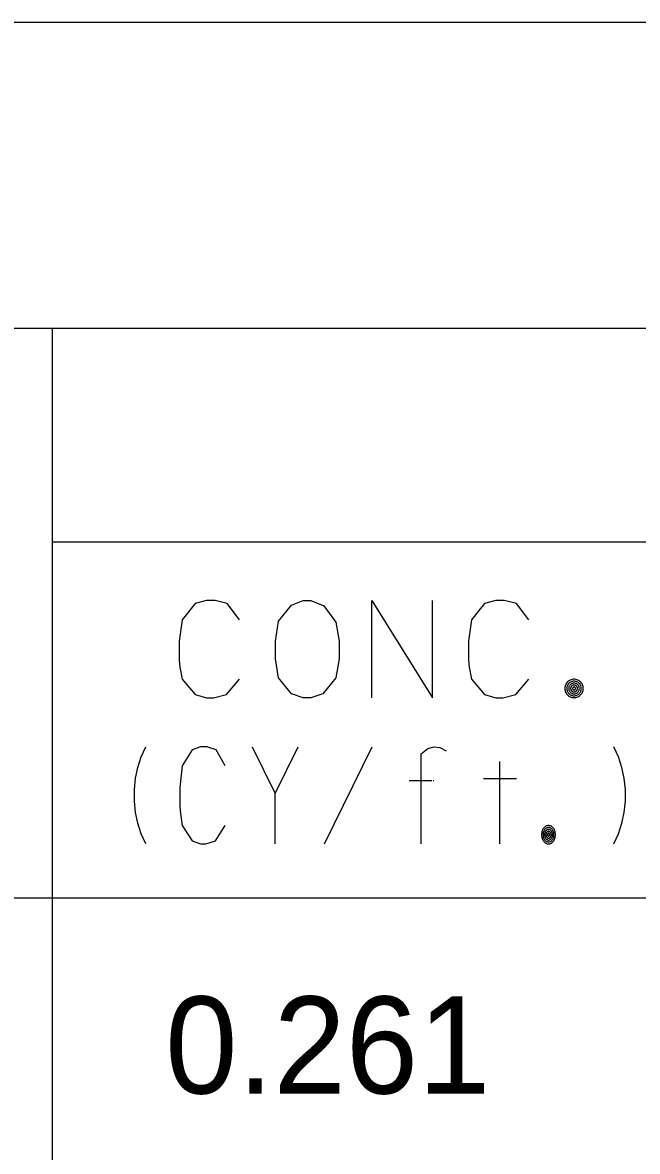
# Model space of a CAD drawing. Extents: x 635698 to 639877, y 296617 to 300175.
# Drawn here: x 639271.19 to 639290.16, y 299135.92 to 299170.8 of the extents above; entities that cross this region are included whole.
import ezdxf

# ---------------------------------------------------------------- set-up
doc = ezdxf.new("R2010")
doc.units = 0
doc.layers.add('1', color=7, linetype='Continuous')
doc.layers.add('3', color=7, linetype='Continuous')

msp = doc.modelspace()

# ---------------------------------------------------------------- linework, layer by layer
at = {"layer": '1'}
for p, q in [((639412.368, 299170.796), (638860.564, 299170.796)), ((639412.368, 299161.344), (639008.767, 299161.344)), ((639272.1, 299161.344), (639272.1, 299029.334)), ((639412.368, 299154.742), (639272.1, 299154.742)), ((639412.368, 299143.742), (639008.767, 299143.742))]:
    msp.add_line(p, q, dxfattribs=at)
at = {"layer": '3'}
for points in [[(639277.883, 299152.348), (639277.506, 299152.844), (639277.128, 299152.939), (639276.868, 299152.939), (639276.513, 299152.844), (639276.112, 299152.348), (639276.017, 299151.687), (639276.017, 299151.333), (639276.017, 299151.096), (639276.041, 299150.884), (639276.112, 299150.506), (639276.513, 299150.033), (639276.868, 299149.939), (639277.08, 299149.939), (639277.482, 299150.033), (639277.883, 299150.506)], [(639279.844, 299152.939), (639280.08, 299152.939), (639280.482, 299152.774), (639280.86, 299152.277), (639280.954, 299151.687), (639280.954, 299151.144), (639280.86, 299150.553), (639280.458, 299150.057), (639280.08, 299149.939), (639279.844, 299149.939), (639279.49, 299150.057), (639279.088, 299150.553), (639278.994, 299151.144), (639278.994, 299151.687), (639279.088, 299152.301), (639279.49, 299152.797), (639279.844, 299152.939)], [(639281.97, 299149.939), (639281.97, 299152.939), (639283.836, 299149.939), (639283.836, 299152.939)], [(639286.813, 299152.348), (639286.435, 299152.844), (639286.057, 299152.939), (639285.797, 299152.939), (639285.443, 299152.844), (639285.041, 299152.348), (639284.947, 299151.687), (639284.947, 299151.333), (639284.947, 299151.096), (639284.971, 299150.884), (639285.041, 299150.506), (639285.443, 299150.033), (639285.797, 299149.939), (639286.01, 299149.939), (639286.411, 299150.033), (639286.813, 299150.506)], [(639288.493, 299150.224), (639288.492, 299150.253), (639288.487, 299150.283), (639288.479, 299150.312), (639288.469, 299150.339), (639288.455, 299150.366), (639288.439, 299150.391), (639288.42, 299150.414), (639288.399, 299150.435), (639288.376, 299150.454), (639288.351, 299150.471), (639288.324, 299150.484), (639288.296, 299150.495), (639288.268, 299150.502), (639288.238, 299150.507), (639288.208, 299150.509), (639288.178, 299150.507), (639288.149, 299150.502), (639288.12, 299150.495), (639288.092, 299150.484), (639288.066, 299150.471), (639288.041, 299150.454), (639288.018, 299150.435), (639287.996, 299150.414), (639287.978, 299150.391), (639287.962, 299150.366), (639287.948, 299150.339), (639287.937, 299150.312), (639287.93, 299150.283), (639287.925, 299150.253), (639287.923, 299150.224), (639287.925, 299150.194), (639287.93, 299150.164), (639287.937, 299150.135), (639287.948, 299150.108), (639287.962, 299150.081), (639287.978, 299150.056), (639287.996, 299150.033), (639288.018, 299150.012), (639288.041, 299149.993), (639288.066, 299149.977), (639288.092, 299149.963), (639288.12, 299149.953), (639288.149, 299149.945), (639288.178, 299149.94), (639288.208, 299149.939), (639288.238, 299149.94), (639288.268, 299149.945), (639288.296, 299149.953), (639288.324, 299149.963), (639288.351, 299149.977), (639288.376, 299149.993), (639288.399, 299150.012), (639288.42, 299150.033), (639288.439, 299150.056), (639288.455, 299150.081), (639288.469, 299150.108), (639288.479, 299150.135), (639288.487, 299150.164), (639288.492, 299150.194), (639288.493, 299150.224)], [(639288.433, 299150.224), (639288.432, 299150.247), (639288.428, 299150.27), (639288.422, 299150.293), (639288.414, 299150.315), (639288.403, 299150.336), (639288.39, 299150.356), (639288.375, 299150.374), (639288.359, 299150.391), (639288.341, 299150.406), (639288.321, 299150.419), (639288.3, 299150.429), (639288.278, 299150.438), (639288.255, 299150.444), (639288.232, 299150.447), (639288.208, 299150.449), (639288.185, 299150.447), (639288.162, 299150.444), (639288.139, 299150.438), (639288.117, 299150.429), (639288.096, 299150.419), (639288.076, 299150.406), (639288.058, 299150.391), (639288.041, 299150.374), (639288.026, 299150.356), (639288.014, 299150.336), (639288.003, 299150.315), (639287.994, 299150.293), (639287.988, 299150.27), (639287.985, 299150.247), (639287.983, 299150.224), (639287.985, 299150.2), (639287.988, 299150.177), (639287.994, 299150.154), (639288.003, 299150.132), (639288.014, 299150.111), (639288.026, 299150.092), (639288.041, 299150.073), (639288.058, 299150.056), (639288.076, 299150.042), (639288.096, 299150.029), (639288.117, 299150.018), (639288.139, 299150.01), (639288.162, 299150.004), (639288.185, 299150), (639288.208, 299149.999), (639288.232, 299150), (639288.255, 299150.004), (639288.278, 299150.01), (639288.3, 299150.018), (639288.321, 299150.029), (639288.341, 299150.042), (639288.359, 299150.056), (639288.375, 299150.073), (639288.39, 299150.092), (639288.403, 299150.111), (639288.414, 299150.132), (639288.422, 299150.154), (639288.428, 299150.177), (639288.432, 299150.2), (639288.433, 299150.224)], [(639288.373, 299150.224), (639288.372, 299150.241), (639288.37, 299150.258), (639288.365, 299150.275), (639288.359, 299150.291), (639288.351, 299150.306), (639288.342, 299150.321), (639288.331, 299150.334), (639288.319, 299150.346), (639288.305, 299150.357), (639288.291, 299150.367), (639288.275, 299150.374), (639288.259, 299150.38), (639288.242, 299150.385), (639288.226, 299150.388), (639288.208, 299150.389), (639288.191, 299150.388), (639288.174, 299150.385), (639288.157, 299150.38), (639288.141, 299150.374), (639288.126, 299150.367), (639288.111, 299150.357), (639288.098, 299150.346), (639288.086, 299150.334), (639288.075, 299150.321), (639288.066, 299150.306), (639288.058, 299150.291), (639288.051, 299150.275), (639288.047, 299150.258), (639288.044, 299150.241), (639288.043, 299150.224), (639288.044, 299150.207), (639288.047, 299150.189), (639288.051, 299150.173), (639288.058, 299150.156), (639288.066, 299150.141), (639288.075, 299150.127), (639288.086, 299150.113), (639288.098, 299150.101), (639288.111, 299150.09), (639288.126, 299150.081), (639288.141, 299150.073), (639288.157, 299150.067), (639288.174, 299150.062), (639288.191, 299150.06), (639288.208, 299150.059), (639288.226, 299150.06), (639288.242, 299150.062), (639288.259, 299150.067), (639288.275, 299150.073), (639288.291, 299150.081), (639288.305, 299150.09), (639288.319, 299150.101), (639288.331, 299150.113), (639288.342, 299150.127), (639288.351, 299150.141), (639288.359, 299150.156), (639288.365, 299150.173), (639288.37, 299150.189), (639288.372, 299150.207), (639288.373, 299150.224)], [(639288.313, 299150.224), (639288.313, 299150.235), (639288.311, 299150.245), (639288.308, 299150.256), (639288.304, 299150.266), (639288.299, 299150.276), (639288.293, 299150.285), (639288.286, 299150.294), (639288.279, 299150.302), (639288.27, 299150.309), (639288.261, 299150.315), (639288.251, 299150.32), (639288.241, 299150.323), (639288.23, 299150.326), (639288.219, 299150.328), (639288.208, 299150.328), (639288.197, 299150.328), (639288.186, 299150.326), (639288.176, 299150.323), (639288.166, 299150.32), (639288.156, 299150.315), (639288.146, 299150.309), (639288.138, 299150.302), (639288.13, 299150.294), (639288.123, 299150.285), (639288.117, 299150.276), (639288.112, 299150.266), (639288.108, 299150.256), (639288.105, 299150.245), (639288.104, 299150.235), (639288.103, 299150.224), (639288.104, 299150.213), (639288.105, 299150.202), (639288.108, 299150.191), (639288.112, 299150.181), (639288.117, 299150.171), (639288.123, 299150.162), (639288.13, 299150.153), (639288.138, 299150.146), (639288.146, 299150.139), (639288.156, 299150.133), (639288.166, 299150.128), (639288.176, 299150.124), (639288.186, 299150.121), (639288.197, 299150.119), (639288.208, 299150.119), (639288.219, 299150.119), (639288.23, 299150.121), (639288.241, 299150.124), (639288.251, 299150.128), (639288.261, 299150.133), (639288.27, 299150.139), (639288.279, 299150.146), (639288.286, 299150.153), (639288.293, 299150.162), (639288.299, 299150.171), (639288.304, 299150.181), (639288.308, 299150.191), (639288.311, 299150.202), (639288.313, 299150.213), (639288.313, 299150.224)], [(639288.253, 299150.224), (639288.253, 299150.229), (639288.252, 299150.233), (639288.251, 299150.238), (639288.249, 299150.242), (639288.247, 299150.246), (639288.245, 299150.25), (639288.242, 299150.254), (639288.238, 299150.257), (639288.235, 299150.26), (639288.231, 299150.263), (639288.227, 299150.265), (639288.222, 299150.267), (639288.218, 299150.268), (639288.213, 299150.268), (639288.208, 299150.269), (639288.204, 299150.268), (639288.199, 299150.268), (639288.194, 299150.267), (639288.19, 299150.265), (639288.186, 299150.263), (639288.182, 299150.26), (639288.178, 299150.257), (639288.175, 299150.254), (639288.172, 299150.25), (639288.169, 299150.246), (639288.167, 299150.242), (639288.166, 299150.238), (639288.164, 299150.233), (639288.164, 299150.229), (639288.163, 299150.224), (639288.164, 299150.219), (639288.164, 299150.214), (639288.166, 299150.21), (639288.167, 299150.205), (639288.169, 299150.201), (639288.172, 299150.197), (639288.175, 299150.194), (639288.178, 299150.19), (639288.182, 299150.187), (639288.186, 299150.185), (639288.19, 299150.182), (639288.194, 299150.181), (639288.199, 299150.18), (639288.204, 299150.179), (639288.208, 299150.179), (639288.213, 299150.179), (639288.218, 299150.18), (639288.222, 299150.181), (639288.227, 299150.182), (639288.231, 299150.185), (639288.235, 299150.187), (639288.238, 299150.19), (639288.242, 299150.194), (639288.245, 299150.197), (639288.247, 299150.201), (639288.249, 299150.205), (639288.251, 299150.21), (639288.252, 299150.214), (639288.253, 299150.219), (639288.253, 299150.224)], [(639274.993, 299145.421), (639274.852, 299145.728), (639274.745, 299146.059), (639274.675, 299146.389), (639274.639, 299146.743), (639274.639, 299147.098), (639274.675, 299147.452), (639274.745, 299147.783), (639274.852, 299148.113), (639274.993, 299148.421)], [(639277.445, 299147.83), (639277.162, 299148.326), (639276.878, 299148.421), (639276.683, 299148.421), (639276.418, 299148.326), (639276.116, 299147.83), (639276.045, 299147.169), (639276.045, 299146.814), (639276.045, 299146.578), (639276.063, 299146.365), (639276.116, 299145.987), (639276.418, 299145.515), (639276.683, 299145.421), (639276.842, 299145.421), (639277.144, 299145.515), (639277.445, 299145.987)], [(639278.278, 299148.421), (639278.986, 299146.98), (639279.695, 299148.421)], [(639280.51, 299145.421), (639281.98, 299148.421)], [(639283.487, 299145.421), (639283.487, 299148.208), (639283.699, 299148.373), (639283.894, 299148.421), (639284.071, 299148.397), (639284.266, 299148.302)], [(639289.44, 299145.421), (639289.582, 299145.728), (639289.688, 299146.059), (639289.759, 299146.389), (639289.794, 299146.743), (639289.794, 299147.098), (639289.759, 299147.452), (639289.688, 299147.783), (639289.582, 299148.113), (639289.44, 299148.421)], [(639285.914, 299145.421), (639285.914, 299147.972)], [(639283.115, 299147.381), (639283.823, 299147.381)], [(639283.859, 299147.381), (639283.876, 299147.381)], [(639286.428, 299147.429), (639285.418, 299147.429)], [(639278.986, 299145.421), (639278.986, 299146.98)], [(639287.635, 299145.706), (639287.634, 299145.735), (639287.63, 299145.765), (639287.624, 299145.793), (639287.616, 299145.821), (639287.606, 299145.848), (639287.594, 299145.873), (639287.58, 299145.896), (639287.564, 299145.917), (639287.547, 299145.936), (639287.528, 299145.952), (639287.508, 299145.966), (639287.487, 299145.977), (639287.466, 299145.984), (639287.443, 299145.989), (639287.421, 299145.99), (639287.399, 299145.989), (639287.377, 299145.984), (639287.355, 299145.977), (639287.334, 299145.966), (639287.314, 299145.952), (639287.295, 299145.936), (639287.278, 299145.917), (639287.262, 299145.896), (639287.248, 299145.873), (639287.236, 299145.848), (639287.226, 299145.821), (639287.218, 299145.793), (639287.212, 299145.765), (639287.209, 299145.735), (639287.207, 299145.706), (639287.209, 299145.675), (639287.212, 299145.646), (639287.218, 299145.617), (639287.226, 299145.589), (639287.236, 299145.563), (639287.248, 299145.538), (639287.262, 299145.515), (639287.278, 299145.493), (639287.295, 299145.475), (639287.314, 299145.459), (639287.334, 299145.445), (639287.355, 299145.435), (639287.377, 299145.427), (639287.399, 299145.422), (639287.421, 299145.421), (639287.443, 299145.422), (639287.466, 299145.427), (639287.487, 299145.435), (639287.508, 299145.445), (639287.528, 299145.459), (639287.547, 299145.475), (639287.564, 299145.493), (639287.58, 299145.515), (639287.594, 299145.538), (639287.606, 299145.563), (639287.616, 299145.589), (639287.624, 299145.617), (639287.63, 299145.646), (639287.634, 299145.675), (639287.635, 299145.706)], [(639287.59, 299145.706), (639287.589, 299145.729), (639287.586, 299145.752), (639287.582, 299145.775), (639287.575, 299145.797), (639287.567, 299145.818), (639287.558, 299145.838), (639287.546, 299145.856), (639287.534, 299145.873), (639287.52, 299145.888), (639287.505, 299145.9), (639287.49, 299145.911), (639287.473, 299145.919), (639287.456, 299145.926), (639287.439, 299145.929), (639287.421, 299145.93), (639287.404, 299145.929), (639287.386, 299145.926), (639287.369, 299145.919), (639287.352, 299145.911), (639287.337, 299145.9), (639287.322, 299145.888), (639287.308, 299145.873), (639287.296, 299145.856), (639287.285, 299145.838), (639287.275, 299145.818), (639287.267, 299145.797), (639287.26, 299145.775), (639287.256, 299145.752), (639287.253, 299145.729), (639287.252, 299145.706), (639287.253, 299145.682), (639287.256, 299145.659), (639287.26, 299145.636), (639287.267, 299145.614), (639287.275, 299145.593), (639287.285, 299145.573), (639287.296, 299145.555), (639287.308, 299145.538), (639287.322, 299145.524), (639287.337, 299145.511), (639287.352, 299145.5), (639287.369, 299145.491), (639287.386, 299145.485), (639287.404, 299145.482), (639287.421, 299145.48), (639287.439, 299145.482), (639287.456, 299145.485), (639287.473, 299145.491), (639287.49, 299145.5), (639287.505, 299145.511), (639287.52, 299145.524), (639287.534, 299145.538), (639287.546, 299145.555), (639287.558, 299145.573), (639287.567, 299145.593), (639287.575, 299145.614), (639287.582, 299145.636), (639287.586, 299145.659), (639287.589, 299145.682), (639287.59, 299145.706)], [(639287.545, 299145.706), (639287.544, 299145.723), (639287.542, 299145.74), (639287.539, 299145.756), (639287.534, 299145.773), (639287.528, 299145.788), (639287.521, 299145.803), (639287.513, 299145.816), (639287.504, 299145.828), (639287.494, 299145.839), (639287.483, 299145.848), (639287.471, 299145.856), (639287.459, 299145.862), (639287.447, 299145.867), (639287.434, 299145.87), (639287.421, 299145.87), (639287.408, 299145.87), (639287.395, 299145.867), (639287.383, 299145.862), (639287.371, 299145.856), (639287.359, 299145.848), (639287.348, 299145.839), (639287.338, 299145.828), (639287.329, 299145.816), (639287.321, 299145.803), (639287.314, 299145.788), (639287.308, 299145.773), (639287.303, 299145.756), (639287.3, 299145.74), (639287.298, 299145.723), (639287.297, 299145.706), (639287.298, 299145.688), (639287.3, 299145.671), (639287.303, 299145.655), (639287.308, 299145.638), (639287.314, 299145.623), (639287.321, 299145.608), (639287.329, 299145.595), (639287.338, 299145.583), (639287.348, 299145.572), (639287.359, 299145.563), (639287.371, 299145.555), (639287.383, 299145.548), (639287.395, 299145.544), (639287.408, 299145.541), (639287.421, 299145.54), (639287.434, 299145.541), (639287.447, 299145.544), (639287.459, 299145.548), (639287.471, 299145.555), (639287.483, 299145.563), (639287.494, 299145.572), (639287.504, 299145.583), (639287.513, 299145.595), (639287.521, 299145.608), (639287.528, 299145.623), (639287.534, 299145.638), (639287.539, 299145.655), (639287.542, 299145.671), (639287.544, 299145.688), (639287.545, 299145.706)], [(639287.5, 299145.706), (639287.499, 299145.716), (639287.498, 299145.727), (639287.496, 299145.738), (639287.493, 299145.748), (639287.489, 299145.758), (639287.485, 299145.767), (639287.48, 299145.776), (639287.474, 299145.784), (639287.467, 299145.79), (639287.46, 299145.796), (639287.453, 299145.801), (639287.445, 299145.805), (639287.437, 299145.808), (639287.429, 299145.81), (639287.421, 299145.81), (639287.413, 299145.81), (639287.405, 299145.808), (639287.397, 299145.805), (639287.389, 299145.801), (639287.382, 299145.796), (639287.375, 299145.79), (639287.368, 299145.784), (639287.363, 299145.776), (639287.357, 299145.767), (639287.353, 299145.758), (639287.349, 299145.748), (639287.346, 299145.738), (639287.344, 299145.727), (639287.343, 299145.716), (639287.342, 299145.706), (639287.343, 299145.695), (639287.344, 299145.684), (639287.346, 299145.673), (639287.349, 299145.663), (639287.353, 299145.653), (639287.357, 299145.644), (639287.363, 299145.635), (639287.368, 299145.628), (639287.375, 299145.621), (639287.382, 299145.614), (639287.389, 299145.61), (639287.397, 299145.606), (639287.405, 299145.603), (639287.413, 299145.601), (639287.421, 299145.6), (639287.429, 299145.601), (639287.437, 299145.603), (639287.445, 299145.606), (639287.453, 299145.61), (639287.46, 299145.614), (639287.467, 299145.621), (639287.474, 299145.628), (639287.48, 299145.635), (639287.485, 299145.644), (639287.489, 299145.653), (639287.493, 299145.663), (639287.496, 299145.673), (639287.498, 299145.684), (639287.499, 299145.695), (639287.5, 299145.706)], [(639287.455, 299145.706), (639287.455, 299145.71), (639287.454, 299145.715), (639287.453, 299145.719), (639287.452, 299145.724), (639287.45, 299145.728), (639287.448, 299145.732), (639287.446, 299145.736), (639287.444, 299145.739), (639287.441, 299145.742), (639287.438, 299145.744), (639287.435, 299145.747), (639287.432, 299145.748), (639287.428, 299145.749), (639287.425, 299145.75), (639287.421, 299145.751), (639287.418, 299145.75), (639287.414, 299145.749), (639287.411, 299145.748), (639287.407, 299145.747), (639287.404, 299145.744), (639287.401, 299145.742), (639287.399, 299145.739), (639287.396, 299145.736), (639287.394, 299145.732), (639287.392, 299145.728), (639287.39, 299145.724), (639287.389, 299145.719), (639287.388, 299145.715), (639287.388, 299145.71), (639287.387, 299145.706), (639287.388, 299145.701), (639287.388, 299145.696), (639287.389, 299145.692), (639287.39, 299145.687), (639287.392, 299145.683), (639287.394, 299145.679), (639287.396, 299145.675), (639287.399, 299145.672), (639287.401, 299145.669), (639287.404, 299145.666), (639287.407, 299145.664), (639287.411, 299145.663), (639287.414, 299145.662), (639287.418, 299145.661), (639287.421, 299145.66), (639287.425, 299145.661), (639287.428, 299145.662), (639287.432, 299145.663), (639287.435, 299145.664), (639287.438, 299145.666), (639287.441, 299145.669), (639287.444, 299145.672), (639287.446, 299145.675), (639287.448, 299145.679), (639287.45, 299145.683), (639287.452, 299145.687), (639287.453, 299145.692), (639287.454, 299145.696), (639287.455, 299145.701), (639287.455, 299145.706)]]:
    msp.add_lwpolyline(points, dxfattribs=at)

# ---------------------------------------------------------------- texts
msp.add_text('0.261', height=2.9989, dxfattribs=at).set_placement((639275.59, 299137.709))

doc.saveas('drawing.dxf')
